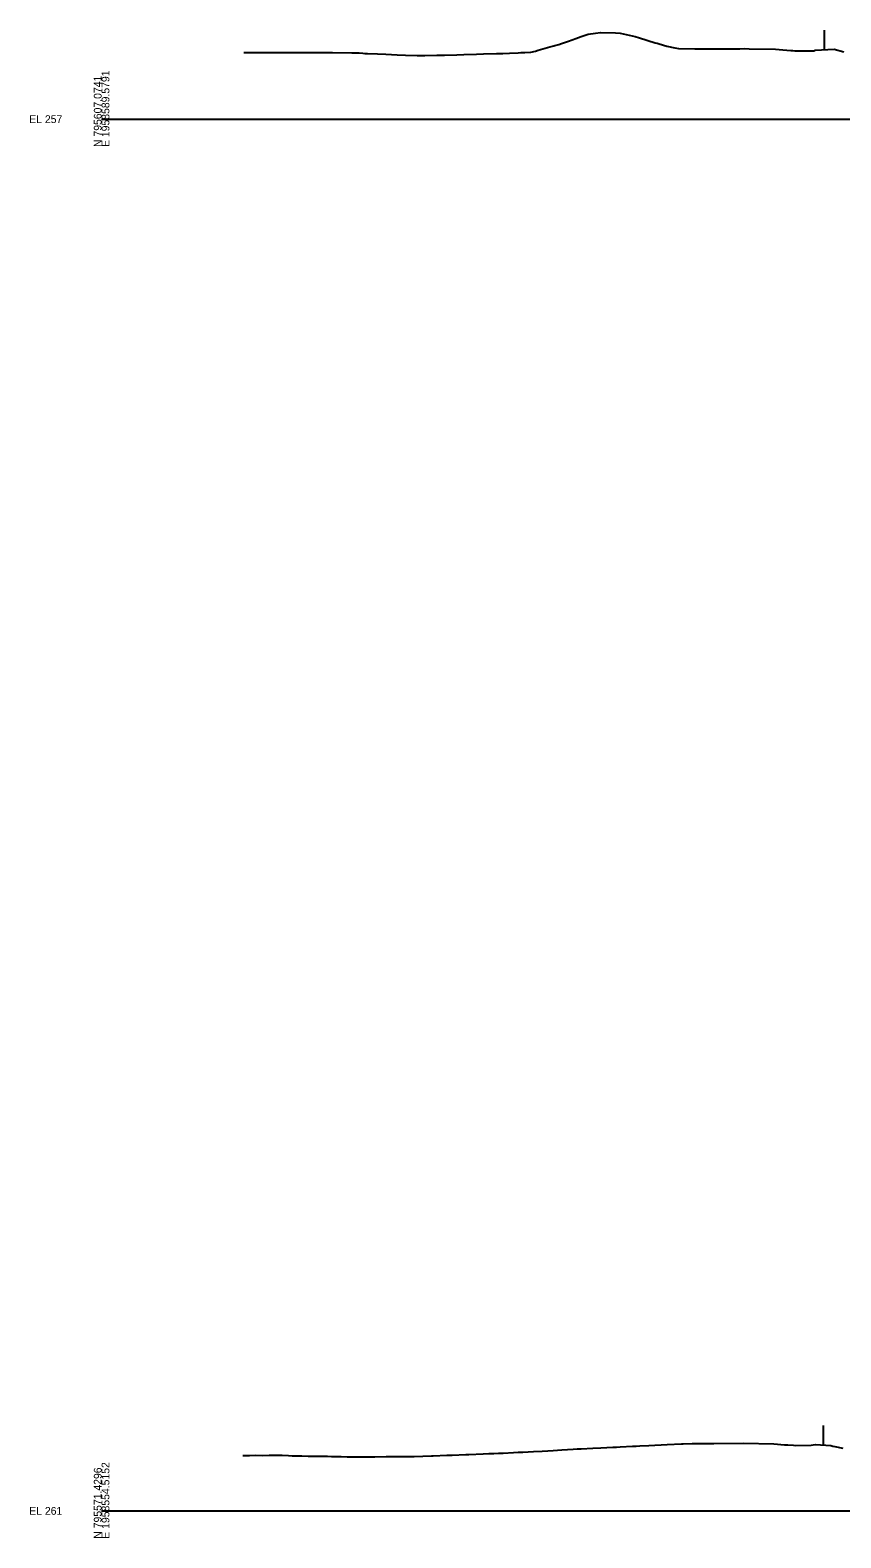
# Model space of a CAD drawing. Extents: x -4026 to 9638, y -10 to 19609.
# Drawn here: x -2026 to -1734, y 8990 to 9532 of the extents above; entities that cross this region are included whole.
import ezdxf

# ---------------------------------------------------------------- set-up
doc = ezdxf.new("R2010")
doc.units = 0
for name, color, linetype in [('Default', 7, 'Continuous'), ('RD_EX_Fence_Other', 7, 'Continuous'), ('RD_GPK_XS_Cell', 7, 'Continuous'), ('RD_XS_ExGround', 7, 'Continuous')]:
    doc.layers.add(name, color=color, linetype=linetype)

msp = doc.modelspace()

# ---------------------------------------------------------------- linework, layer by layer
at = {"layer": 'RD_EX_Fence_Other'}
for p, q in [((-1740.21, 9531.97), (-1740.21, 9524.97)), ((-1740.62, 9030.65), (-1740.62, 9023.65))]:
    msp.add_line(p, q, dxfattribs=at)
at = {"layer": 'RD_GPK_XS_Cell'}
for p, q in [((-2000, 9500), (-1650, 9500)), ((-2000, 9000), (-1650, 9000))]:
    msp.add_line(p, q, dxfattribs=at)
at = {"layer": 'RD_XS_ExGround'}
for points in [[(-1948.81, 9523.95), (-1946.88, 9523.94), (-1943.64, 9523.94), (-1939.86, 9523.94), (-1936.51, 9523.93), (-1932.85, 9523.91), (-1929.38, 9523.9), (-1925.84, 9523.9), (-1922.25, 9523.92), (-1918.82, 9523.9), (-1916.99, 9523.89), (-1910.06, 9523.82), (-1907.44, 9523.78), (-1906.14, 9523.71), (-1905.34, 9523.64), (-1904.8, 9523.61), (-1904.4, 9523.59), (-1900.86, 9523.41), (-1897.78, 9523.29), (-1893.73, 9523.14), (-1890.77, 9523.04), (-1886.6, 9522.9), (-1885.17, 9522.88), (-1883.75, 9522.9), (-1879.47, 9522.93), (-1876.74, 9522.97), (-1872.34, 9523.12), (-1869.73, 9523.21), (-1865.21, 9523.34), (-1862.71, 9523.41), (-1858.08, 9523.53), (-1855.7, 9523.63), (-1853.34, 9523.75), (-1850.22, 9523.87), (-1849.31, 9523.9), (-1847.81, 9523.96), (-1845.66, 9524.03), (-1844.04, 9524.47), (-1843.05, 9524.73), (-1838.8, 9525.97), (-1837.94, 9526.2), (-1837.41, 9526.36), (-1837.04, 9526.47), (-1835.67, 9526.84), (-1834.66, 9527.15), (-1832.13, 9527.97), (-1829.56, 9529.03), (-1828.6, 9529.39), (-1827.64, 9529.7), (-1825.06, 9530.57), (-1822.43, 9530.9), (-1820.63, 9531.19), (-1815.3, 9531.07), (-1813.62, 9530.89), (-1808.17, 9529.66), (-1806.6, 9529.21), (-1801.04, 9527.46), (-1800.31, 9527.28), (-1799.59, 9527.04), (-1796.77, 9526.25), (-1793.91, 9525.61), (-1792.58, 9525.43), (-1786.78, 9525.24), (-1786.17, 9525.25), (-1785.17, 9525.25), (-1784.82, 9525.24), (-1784.08, 9525.24), (-1781.66, 9525.24), (-1779.83, 9525.23), (-1770.53, 9525.31), (-1768.8, 9525.33), (-1767.16, 9525.29), (-1757.73, 9525.09), (-1755.05, 9524.88), (-1752.27, 9524.67), (-1751.44, 9524.61), (-1750.81, 9524.56), (-1750.49, 9524.51), (-1744, 9524.59), (-1743.48, 9524.75), (-1736.67, 9525.14), (-1733.13, 9524.18)], [(-1949.22, 9019.92), (-1946.79, 9019.95), (-1944.56, 9019.96), (-1942.15, 9019.94), (-1939.77, 9019.97), (-1938.61, 9019.96), (-1937.43, 9019.98), (-1935.08, 9020.02), (-1932.76, 9019.9), (-1931.54, 9019.83), (-1930.3, 9019.8), (-1928, 9019.72), (-1925.75, 9019.69), (-1923.17, 9019.66), (-1918.73, 9019.6), (-1917.4, 9019.59), (-1916.04, 9019.56), (-1913.86, 9019.53), (-1911.72, 9019.46), (-1910.33, 9019.43), (-1908.91, 9019.39), (-1906.79, 9019.36), (-1904.7, 9019.39), (-1901.78, 9019.43), (-1897.69, 9019.5), (-1894.65, 9019.54), (-1892.65, 9019.56), (-1890.68, 9019.57), (-1889.11, 9019.57), (-1887.66, 9019.59), (-1881.38, 9019.79), (-1881.07, 9019.8), (-1880.74, 9019.81), (-1875.85, 9019.98), (-1875.53, 9019.99), (-1875.22, 9020.01), (-1874.9, 9020.01), (-1874.58, 9020.02), (-1874.26, 9020.04), (-1873.93, 9020.05), (-1869.08, 9020.24), (-1868.73, 9020.25), (-1867.96, 9020.29), (-1862.82, 9020.5), (-1860.83, 9020.58), (-1859, 9020.64), (-1857.29, 9020.7), (-1855.61, 9020.78), (-1851.87, 9020.97), (-1850.22, 9021.04), (-1848.6, 9021.13), (-1846.68, 9021.23), (-1844.74, 9021.33), (-1841.58, 9021.5), (-1839.61, 9021.62), (-1837.61, 9021.73), (-1836.08, 9021.83), (-1834.57, 9021.91), (-1832.54, 9022.02), (-1830.48, 9022.14), (-1829.01, 9022.23), (-1827.55, 9022.3), (-1823.35, 9022.52), (-1820.54, 9022.66), (-1818.4, 9022.74), (-1816.22, 9022.85), (-1814.86, 9022.9), (-1813.53, 9022.98), (-1809.09, 9023.22), (-1807.79, 9023.29), (-1806.51, 9023.36), (-1803.22, 9023.51), (-1796.68, 9023.83), (-1791.48, 9024.05), (-1790.88, 9024.08), (-1787.7, 9024.18), (-1786.58, 9024.21), (-1784.32, 9024.21), (-1783.28, 9024.2), (-1780.26, 9024.16), (-1779.85, 9024.16), (-1769.27, 9024.32), (-1758.38, 9024.05), (-1754.46, 9023.77), (-1753.33, 9023.7), (-1751.22, 9023.57), (-1750.4, 9023.49), (-1744.92, 9023.57), (-1744.15, 9023.67), (-1743.39, 9023.82), (-1737.79, 9023.48), (-1737.08, 9023.23), (-1736.38, 9023.1), (-1733.54, 9022.57)]]:
    msp.add_lwpolyline(points, dxfattribs=at)

# ---------------------------------------------------------------- texts
at = {"layer": 'Default'}
for p in [(-2000, 9500), (-2000, 9000)]:
    msp.add_text('-', height=0.0001, dxfattribs=at).set_placement(p)
at = {"layer": 'RD_GPK_XS_Cell'}
for s, p in [('E 1958589.5791', (-1997.2, 9490)), ('N 795607.0741', (-2000, 9490)), ('N 795571.4296', (-2000, 8990)), ('E 1958554.5152', (-1997.2, 8990))]:
    msp.add_text(s, height=2.8, rotation=90, dxfattribs=at).set_placement(p)
for s, p in [('EL 257', (-2026, 9498.6)), ('EL 261', (-2026, 8998.6))]:
    msp.add_text(s, height=2.8, dxfattribs=at).set_placement(p)

doc.saveas('drawing.dxf')
